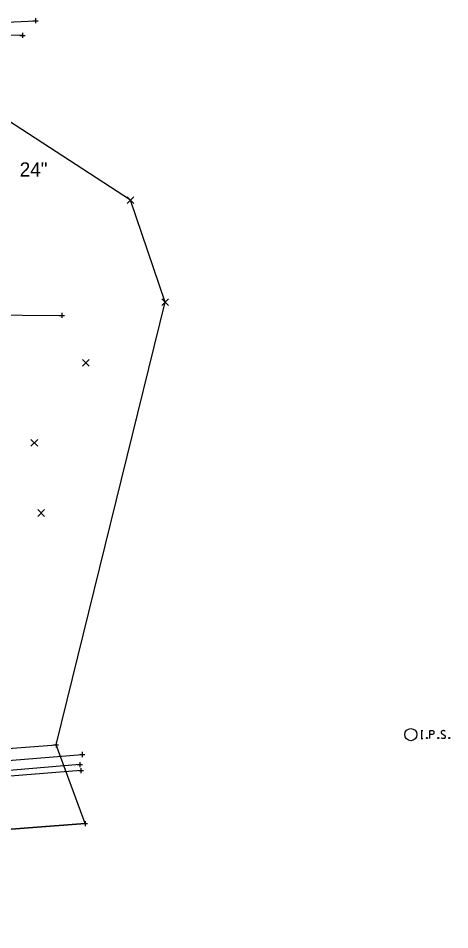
# Model space of a CAD drawing. Extents: x 203564 to 204038, y 344976 to 345157.
# Drawn here: x 203952.6 to 204037.9, y 344976.5 to 345156.9 of the extents above; entities that cross this region are included whole.
import ezdxf

# ---------------------------------------------------------------- set-up
doc = ezdxf.new("R2010")
doc.units = 0
for name, color, linetype in [('_CIVIL_CONSTRUCTION', 7, 'Continuous'), ('PM_X_Channelizing_Line', 7, 'Continuous'), ('RD_X_Fence', 7, 'Continuous'), ('RW_X_CL_100_Bearings', 7, 'Continuous'), ('RW_X_CL_100_Distances', 7, 'Continuous'), ('RW_X_CL_100_Stations', 7, 'Continuous'), ('RW_X_Esmt_LA', 7, 'Continuous'), ('SV_P_Control_Cells_Set', 7, 'Continuous'), ('SV_X_Break_Lines', 7, 'Continuous'), ('SV_X_Edge_of_Slip', 7, 'Continuous'), ('SV_X_Shot_Marker', 7, 'Continuous'), ('SV_X_Terrain_Boundary', 7, 'Continuous'), ('VG_X_Text', 7, 'Continuous')]:
    doc.layers.add(name, color=color, linetype=linetype)

msp = doc.modelspace()

# ---------------------------------------------------------------- linework, layer by layer
at = {"layer": '_CIVIL_CONSTRUCTION'}
for p, q in [((203955.53, 345156.39), (203956.53, 345156.39)), ((203956.03, 345156.89), (203956.03, 345155.89)), ((203956.03, 345156.39), (203956.03, 345156.39)), ((203952.95, 345153.5), (203953.95, 345153.5)), ((203953.45, 345154), (203953.45, 345153)), ((203953.45, 345153.5), (203953.45, 345153.5)), ((203961.23, 345098.58), (203961.23, 345097.58)), ((203960.73, 345098.08), (203961.73, 345098.08)), ((203961.23, 345098.08), (203961.23, 345098.08)), ((203959.58, 345013.12), (203960.58, 345013.12)), ((203960.08, 345013.62), (203960.08, 345012.62)), ((203960.08, 345013.12), (203960.08, 345013.12)), ((203964.76, 345011.21), (203965.76, 345011.21)), ((203965.26, 345011.71), (203965.26, 345010.71)), ((203965.26, 345011.21), (203965.26, 345011.21)), ((203964.29, 345009.21), (203965.29, 345009.21)), ((203964.79, 345009.71), (203964.79, 345008.71)), ((203964.79, 345009.21), (203964.79, 345009.21)), ((203965, 345008.54), (203965, 345007.54)), ((203964.5, 345008.04), (203965.5, 345008.04)), ((203965, 345008.04), (203965, 345008.04)), ((203965.34, 344997.53), (203966.34, 344997.53)), ((203965.34, 344997.53), (203966.34, 344997.53)), ((203965.84, 344998.03), (203965.84, 344997.03)), ((203965.84, 344998.03), (203965.84, 344997.03)), ((203965.84, 344997.53), (203965.84, 344997.53)), ((203965.84, 344997.53), (203965.84, 344997.53))]:
    msp.add_line(p, q, dxfattribs=at)
at = {"layer": 'PM_X_Channelizing_Line'}
msp.add_lwpolyline([(203965.84, 344997.53), (203921.82, 344994.21), (203870.66, 344990.35), (203822.82, 344987.23), (203774.29, 344983.85), (203725.72, 344980.7), (203661.3, 344976.54)], dxfattribs=at)
at = {"layer": 'RD_X_Fence'}
msp.add_lwpolyline([(203689.69, 345139.7), (203694.78, 345139.75), (203716.34, 345141.29), (203756.25, 345143.96), (203801.36, 345146.81), (203831.78, 345149.07), (203859.66, 345150.34), (203911.63, 345153.34), (203944.56, 345155.88), (203956.03, 345156.39)], dxfattribs=at)
at = {"layer": 'RW_X_CL_100_Bearings'}
for p, q in [((203974.16, 345120.24), (203975.5, 345121.58)), ((203974.16, 345121.58), (203975.5, 345120.24)), ((203980.99, 345100.05), (203982.32, 345101.38)), ((203980.99, 345101.38), (203982.32, 345100.05)), ((203965.34, 345088.05), (203966.67, 345089.39)), ((203965.34, 345089.39), (203966.67, 345088.05)), ((203955.13, 345072.23), (203956.47, 345073.57)), ((203955.13, 345073.57), (203956.47, 345072.23)), ((203956.5, 345058.32), (203957.83, 345059.66)), ((203956.5, 345059.66), (203957.83, 345058.32))]:
    msp.add_line(p, q, dxfattribs=at)
at = {"layer": 'RW_X_CL_100_Distances'}
msp.add_lwpolyline([(203964.79, 345009.21), (203920.59, 345005.46), (203869.72, 345001.85), (203821.87, 344998.44), (203773.9, 344995.18), (203724.14, 344991.94), (203661.21, 344987.77)], dxfattribs=at)
at = {"layer": 'RW_X_CL_100_Stations'}
msp.add_lwpolyline([(203660.93, 344989.96), (203723.73, 344994.26), (203773.58, 344997.37), (203821.68, 345000.54), (203869.87, 345003.95), (203920.38, 345007.59), (203965.26, 345011.21)], dxfattribs=at)
at = {"layer": 'RW_X_Esmt_LA'}
msp.add_lwpolyline([(203965.84, 344997.53), (203921.82, 344994.21), (203870.66, 344990.35), (203822.82, 344987.23), (203774.29, 344983.85), (203725.72, 344980.7), (203661.3, 344976.54)], dxfattribs=at)
at = {"layer": 'SV_P_Control_Cells_Set'}
msp.add_lwpolyline([(203965, 345008.04), (203920.69, 345004.51), (203869.77, 345000.84), (203822.11, 344997.28), (203773.93, 344994.18), (203724.2, 344990.95), (203660.85, 344986.88)], dxfattribs=at)
at = {"layer": 'SV_X_Break_Lines'}
for points in [[(203953.45, 345153.5), (203943.72, 345153.64), (203912.05, 345151.95), (203858.96, 345147.7), (203833.76, 345144.76), (203801.31, 345140.81), (203779.13, 345136.66), (203777.12, 345135.45), (203752.42, 345126.52), (203746.41, 345122.24), (203728.59, 345114.72)], [(203661.18, 344992.05), (203683.55, 344993.04), (203711.97, 344996.72), (203761.48, 344999.07), (203779.57, 345000.01), (203798.75, 345001.25), (203821.87, 345002.65), (203840.75, 345003.88), (203854.14, 345005.45), (203866.21, 345006.03), (203879.89, 345007.13), (203922.91, 345010.28), (203960.08, 345013.12)]]:
    msp.add_lwpolyline(points, dxfattribs=at)
at = {"layer": 'SV_X_Edge_of_Slip'}
msp.add_lwpolyline([(203873.61, 345085.03), (203888.59, 345088.45), (203902.81, 345089.36), (203922.29, 345090.53), (203933.14, 345094.04), (203932.52, 345097.67), (203945.54, 345098.18), (203961.23, 345098.08)], dxfattribs=at)
at = {"layer": 'SV_X_Shot_Marker'}
for points in [[(204032.26, 345015.95), (204032.61, 345015.95)], [(204032.43, 345014.35), (204032.43, 345015.95)], [(204034, 345014.35), (204034, 345015.95), (204034.53, 345015.95), (204034.58, 345015.94), (204034.66, 345015.91), (204034.69, 345015.89), (204034.73, 345015.86), (204034.77, 345015.8), (204034.8, 345015.74), (204034.82, 345015.63), (204034.82, 345015.48), (204034.81, 345015.43), (204034.79, 345015.36), (204034.75, 345015.27), (204034.7, 345015.23), (204034.67, 345015.21), (204034.62, 345015.18), (204034.53, 345015.17), (204034, 345015.17)], [(204037.01, 345015.84), (204036.99, 345015.86), (204036.95, 345015.89), (204036.85, 345015.92), (204036.73, 345015.95), (204036.64, 345015.95), (204036.61, 345015.95), (204036.47, 345015.91), (204036.35, 345015.84), (204036.27, 345015.74), (204036.25, 345015.63), (204036.25, 345015.56), (204036.27, 345015.46), (204036.36, 345015.37), (204036.96, 345014.99), (204037.02, 345014.94), (204037.04, 345014.89), (204037.06, 345014.82), (204037.06, 345014.74), (204037.05, 345014.66), (204037.04, 345014.61), (204037.02, 345014.55), (204037, 345014.5), (204036.97, 345014.46), (204036.94, 345014.43), (204036.91, 345014.4), (204036.86, 345014.37), (204036.83, 345014.36), (204036.73, 345014.35), (204036.58, 345014.35), (204036.48, 345014.37), (204036.33, 345014.46), (204036.25, 345014.54)], [(204032.26, 345014.35), (204032.61, 345014.35)], [(204033.39, 345014.56), (204033.45, 345014.56), (204033.48, 345014.54), (204033.51, 345014.49), (204033.51, 345014.43), (204033.48, 345014.37), (204033.45, 345014.35), (204033.39, 345014.35), (204033.36, 345014.37), (204033.33, 345014.43), (204033.33, 345014.49), (204033.36, 345014.54), (204033.39, 345014.56)], [(204035.64, 345014.56), (204035.7, 345014.56), (204035.73, 345014.54), (204035.76, 345014.49), (204035.76, 345014.43), (204035.73, 345014.37), (204035.7, 345014.35), (204035.64, 345014.35), (204035.61, 345014.37), (204035.57, 345014.43), (204035.57, 345014.49), (204035.61, 345014.54), (204035.64, 345014.56)], [(204037.82, 345014.56), (204037.88, 345014.56), (204037.91, 345014.54), (204037.94, 345014.49), (204037.94, 345014.43), (204037.91, 345014.37), (204037.88, 345014.35), (204037.82, 345014.35), (204037.79, 345014.37), (204037.76, 345014.43), (204037.76, 345014.49), (204037.79, 345014.54), (204037.82, 345014.56)]]:
    msp.add_lwpolyline(points, dxfattribs=at)
msp.add_circle((204030.24, 345015.15), 1.2, dxfattribs=at)
at = {"layer": 'SV_X_Terrain_Boundary'}
msp.add_lwpolyline([(203688.25, 345107.3), (203663.45, 345073.36), (203661.3, 344976.54), (203725.72, 344980.7), (203774.29, 344983.85), (203870.66, 344990.35), (203921.82, 344994.21), (203965.84, 344997.53), (203960.08, 345013.12), (203981.66, 345100.71), (203974.83, 345120.91), (203950.66, 345136.61), (203932.67, 345155.23), (203932.67, 345155.29), (203859.66, 345150.34), (203831.78, 345149.07), (203795.84, 345146.71), (203756.25, 345143.96), (203689.69, 345139.7)], close=True, dxfattribs=at)

# ---------------------------------------------------------------- texts
at = {"layer": 'VG_X_Text'}
msp.add_text('24"', height=2.8, dxfattribs=at).set_placement((203952.9, 345125.57))

doc.saveas('drawing.dxf')
